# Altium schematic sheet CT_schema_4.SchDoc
size 313 x 185 mm
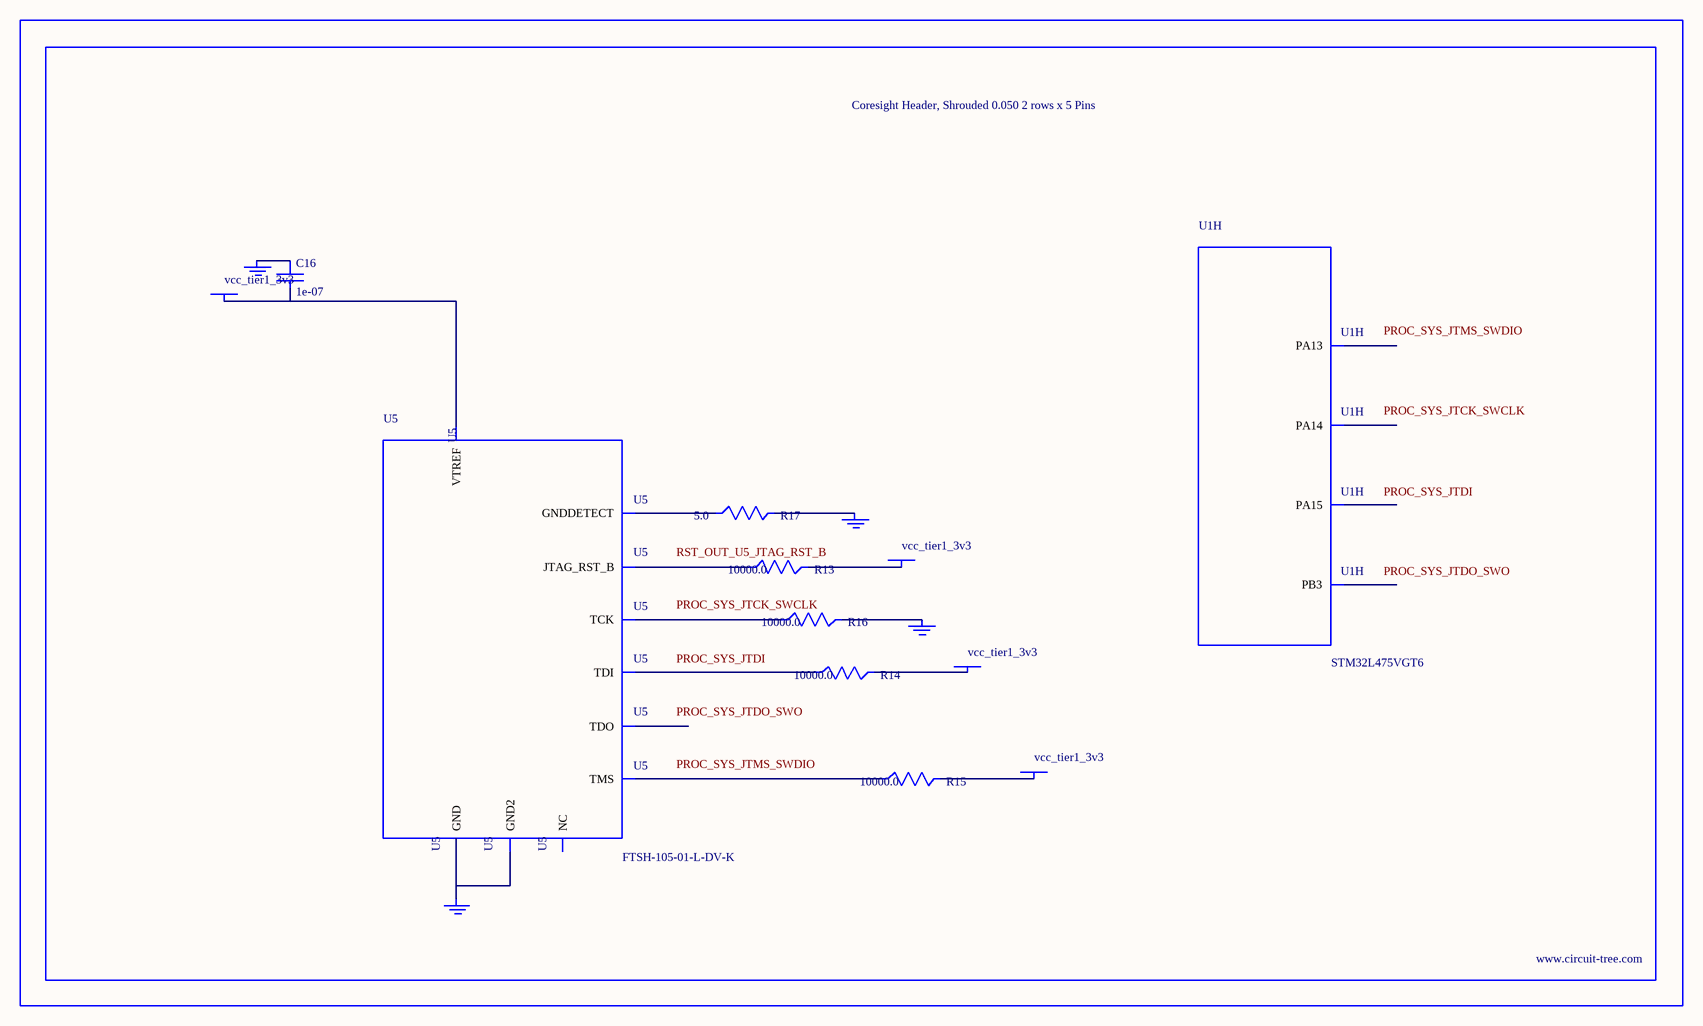
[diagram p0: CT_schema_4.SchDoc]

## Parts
BORDER3  (no value)
C16  1e-07  [C0402]
GND_INSTANCE_3_0  (no value)
GND_INSTANCE_3_1  (no value)
GND_INSTANCE_3_2  (no value)
GND_INSTANCE_3_3  (no value)
POWER_INSTANCE_3_0  vcc_tier1_3v3
POWER_INSTANCE_3_1  vcc_tier1_3v3
POWER_INSTANCE_3_2  vcc_tier1_3v3
POWER_INSTANCE_3_3  vcc_tier1_3v3
R13  10000.0  [R0603]
R14  10000.0  [R0603]
R15  10000.0  [R0603]
R16  10000.0  [R0603]
R17  5.0  [R0603]
U1  STM32L475VGT6  [LQFP100]  (part H of 11)
U5  FTSH-105-01-L-DV-K  [SAMTEC_FTSH-105-01-L-DV-K]

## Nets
NetC16_1: C16.1 GND_INSTANCE_3_0.0(GND)
NetC16_2: C16.2 POWER_INSTANCE_3_0.0(PWR) U5.1(VTREF)
NetGND_INSTANCE_3_1_0: GND_INSTANCE_3_1.0(GND) R16.2
NetGND_INSTANCE_3_2_0: GND_INSTANCE_3_2.0(GND) R17.2
NetGND_INSTANCE_3_3_0: GND_INSTANCE_3_3.0(GND) U5.3(GND) U5.5(GND2)
NetPOWER_INSTANCE_3_1_0: POWER_INSTANCE_3_1.0(PWR) R15.2
NetPOWER_INSTANCE_3_2_0: POWER_INSTANCE_3_2.0(PWR) R14.2
NetPOWER_INSTANCE_3_3_0: POWER_INSTANCE_3_3.0(PWR) R13.2
NetR13_1: R13.1 U5.10(JTAG_RST_B)
NetR14_1: R14.1 U5.8(TDI)
NetR15_1: R15.1 U5.2(TMS)
NetR16_1: R16.1 U5.4(TCK)
NetR17_1: R17.1 U5.9(GNDDETECT)

Not connected (* = marked no-connect by the designer): U1 72(PA13) 76(PA14) 77(PA15) 89(PB3); U5 6(TDO) 7(NC)

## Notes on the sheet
- Labels drawn without touching a wire or pin: PROC_SYS_JTCK_SWCLK, PROC_SYS_JTDI, PROC_SYS_JTDO_SWO, PROC_SYS_JTMS_SWDIO, RST_OUT_U5_JTAG_RST_B

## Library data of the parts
BORDER3 = BORDER_PAGE3
C16 = C0402C104K3RACTU
GND_INSTANCE_3_0-GND_INSTANCE_3_3 = GND
POWER_INSTANCE_3_0-POWER_INSTANCE_3_3 = PWR
R13-R16 = RC0603JR-0710KL
R17 = ERJ-3GEYJ5R1V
